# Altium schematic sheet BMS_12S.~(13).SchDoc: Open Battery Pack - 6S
size A3; Author: Morgane Vallée; Revision: 1.0; SheetNumber: 3; SheetTotal: 4
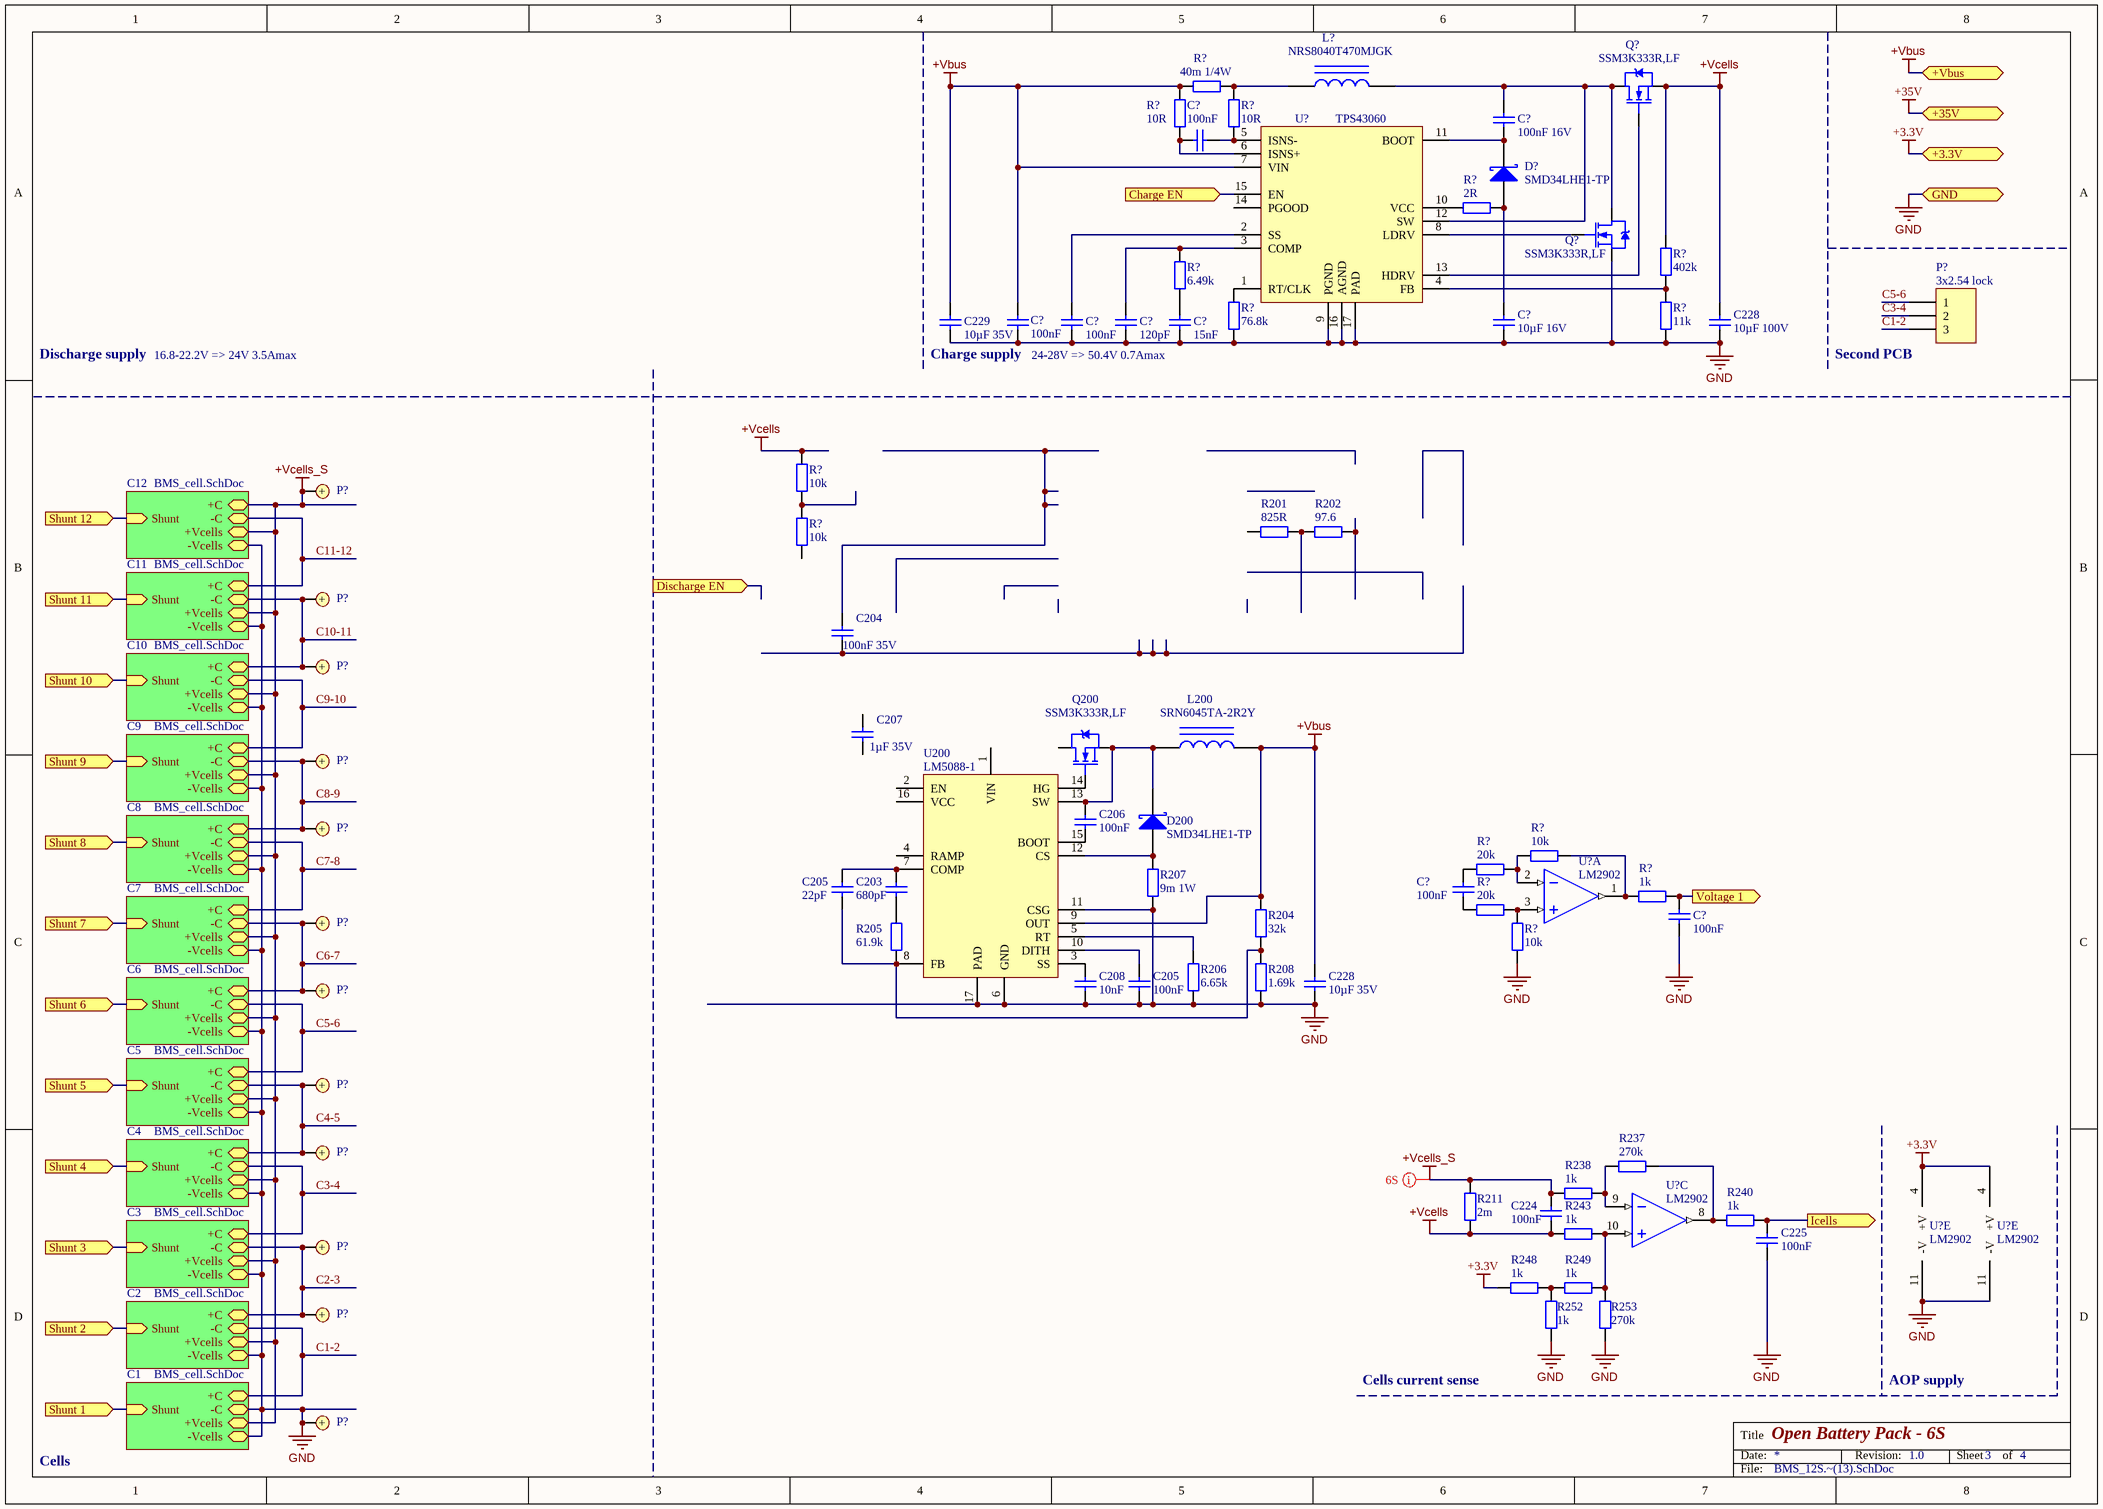
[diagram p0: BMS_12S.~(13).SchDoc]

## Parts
(Parts that share a designator on the sheet are numbered #1, #2 ... from top to bottom, then left to right.)
C203  680pF  [C0603]
C204  100nF 35V  [C0603]
C205#1  22pF  [C0603]
C205#2  100nF  [C0603]
C206  100nF  [C0603]
C207  1µF 35V  [C0805]
C208  10nF  [C0603]
C224  100nF  [C0603]
C225  100nF  [C0603]
C228#1  10µF 100V  [C0603]
C228#2  10µF 35V  [C0603]
C229  10µF 35V  [C0603]
C?#1  100nF 16V  [C0603]
C?#2  100nF  [C0603]
C?#3  100nF  [C0603]
C?#4  120pF  [C0603]
C?#5  15nF  [C0603]
C?#6  10µF 16V  [C0805]
C?#7  100nF  [C0603]
C?#8  100nF  [C0603]
C?#9  100nF  [C0603]
D200  SMD34LHE1-TP  [SOD-123H]
D?  SMD34LHE1-TP  [SOD-123H]
L200  SRN6045TA-2R2Y  [SELF_SMD_8x8]
L?  NRS8040T470MJGK  [SELF_SMD_8x8]
P?#1  3x2.54 lock  [MOLEX KK 0022272031]
P?#2  Bat+  [Keystone 241]  (value not drawn)
P?#3  Bat+  [Keystone 241]  (value not drawn)
P?#4  Bat+  [Keystone 241]  (value not drawn)
P?#5  Bat+  [Keystone 241]  (value not drawn)
P?#6  Bat+  [Keystone 241]  (value not drawn)
P?#7  Bat+  [Keystone 241]  (value not drawn)
P?#8  Bat+  [Keystone 241]  (value not drawn)
P?#9  Bat+  [Keystone 241]  (value not drawn)
P?#10  Bat+  [Keystone 241]  (value not drawn)
P?#11  Bat+  [Keystone 241]  (value not drawn)
P?#12  Bat+  [Keystone 241]  (value not drawn)
P?#13  Bat+  [Keystone 241]  (value not drawn)
Q200  SSM3K333R,LF  [TI SOT-23-3 DBZ]
Q?#1  SSM3K333R,LF  [TI SOT-23-3 DBZ]
Q?#2  SSM3K333R,LF  [TI SOT-23-3 DBZ]
R201  825R  [R0603]
R202  97.6  [R0603]
R204  32k  [R0603]
R205  61.9k  [R0603]
R206  6.65k  [R0603]
R207  9m 1W  [R1206]
R208  1.69k  [R0603]
R211  2m  [R1206]
R237  270k  [R0603]
R238  1k  [R0603]
R240  1k  [R0603]
R243  1k  [R0603]
R248  1k  [R0603]
R249  1k  [R0603]
R252  1k  [R0603]
R253  270k  [R0603]
R?#1  10R  [R0603]
R?#2  40m 1/4W  [R1206]
R?#3  10R  [R0603]
R?#4  2R  [R0603]
R?#5  402k  [R0603]
R?#6  6.49k  [R0603]
R?#7  76.8k  [R0603]
R?#8  11k  [R0603]
R?#9  10k  [R0603]
R?#10  10k  [R0603]
R?#11  10k  [R0603]
R?#12  20k  [R0603]
R?#13  1k  [R0603]
R?#14  20k  [R0603]
R?#15  10k  [R0603]
U200  LM5088-1  [TI MSOP-10 DGQ]
U?#1  TPS43060  [TI WQFN-16 RGH]
U?#2  LM2902  [Atmel SO-14 14S1]  (part A of 5)
U?#3  LM2902  [Atmel SO-14 14S1]  (part C of 5)
U?#4  LM2902  [Atmel SO-14 14S1]  (part E of 5)
U?#5  LM2902  [Atmel SO-14 14S1]  (part E of 5)

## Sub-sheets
C1 = BMS_cell.SchDoc: -C, +C, +Vcells, -Vcells, Shunt (in)
C2 = BMS_cell.SchDoc: -C, +C, +Vcells, -Vcells, Shunt (in)
C3 = BMS_cell.SchDoc: -C, +C, +Vcells, -Vcells, Shunt (in)
C4 = BMS_cell.SchDoc: -C, +C, +Vcells, -Vcells, Shunt (in)
C5 = BMS_cell.SchDoc: -C, +C, +Vcells, -Vcells, Shunt (in)
C6 = BMS_cell.SchDoc: -C, +C, +Vcells, -Vcells, Shunt (in)
C7 = BMS_cell.SchDoc: -C, +C, +Vcells, -Vcells, Shunt (in)
C8 = BMS_cell.SchDoc: -C, +C, +Vcells, -Vcells, Shunt (in)
C9 = BMS_cell.SchDoc: -C, +C, +Vcells, -Vcells, Shunt (in)
C10 = BMS_cell.SchDoc: -C, +C, +Vcells, -Vcells, Shunt (in)
C11 = BMS_cell.SchDoc: -C, +C, +Vcells, -Vcells, Shunt (in)
C12 = BMS_cell.SchDoc: -C, +C, +Vcells, -Vcells, Shunt (in)

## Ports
+3.3V, +35V, +Vbus, Charge EN (in), Discharge EN (in), GND, Icells (out), Shunt 1 (in), Shunt 2 (in), Shunt 3 (in), Shunt 4 (in), Shunt 5 (in), Shunt 6 (in), Shunt 7 (in), Shunt 8 (in), Shunt 9 (in), Shunt 10 (in), Shunt 11 (in), Shunt 12 (in), Voltage 1 (out)

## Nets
+3.3V: R248.2 U?#4.4(+V) U?#5.4(+V) ; port +3.3V
+Vbus: C228#2.1 C229.1 C?#7.2 L200.2 R204.2 R?#1.1 R?#2.2 U200.9(OUT) U?#1.7(VIN) ; port +Vbus
+Vcells: C224.2 C228#1.1 Q?#1.2(S) R211.1 R243.2 R?#5.2 R?#9.2
+Vcells_S: C224.1 P?#2.1 R211.2 R238.1 ; sheet C1/+Vcells, sheet C2/+Vcells, sheet C3/+Vcells, sheet C4/+Vcells, sheet C5/+Vcells, sheet C6/+Vcells, sheet C7/+Vcells, sheet C8/+Vcells, sheet C9/+Vcells, sheet C10/+Vcells, sheet C11/+Vcells, sheet C12/+C, sheet C12/+Vcells
GND: C205#2.2 C208.2 C225.2 C228#1.2 C228#2.2 C229.2 C?#3.2 C?#4.2 C?#5.2 C?#6.2 C?#7.1 C?#9.2 P?#13.1 Q?#2.2(S) R206.1 R207.1 R208.1 R252.2 R253.1 R?#7.1 R?#8.1 R?#15.2 U200.6(GND) U200.11(CSG) U200.17(PAD) U?#1.9(PGND) U?#1.16(AGND) U?#1.17(PAD) U?#4.11(-V) U?#5.11(-V) ; port GND, sheet C1/-C, sheet C1/-Vcells, sheet C2/-Vcells, sheet C3/-Vcells, sheet C4/-Vcells, sheet C5/-Vcells, sheet C6/-Vcells, sheet C7/-Vcells, sheet C8/-Vcells, sheet C9/-Vcells, sheet C10/-Vcells, sheet C11/-Vcells, sheet C12/-Vcells
C1-2: P?#1.3 ; sheet C1/+C, sheet C2/-C
C2-3: P?#11.1 P?#12.1 ; sheet C2/+C, sheet C3/-C
C3-4: P?#1.2 ; sheet C3/+C, sheet C4/-C
C4-5: P?#9.1 P?#10.1 ; sheet C4/+C, sheet C5/-C
C5-6: P?#1.1 ; sheet C5/+C, sheet C6/-C
C6-7: P?#7.1 P?#8.1 ; sheet C6/+C, sheet C7/-C
C7-8: sheet C7/+C, sheet C8/-C
C8-9: P?#5.1 P?#6.1 ; sheet C8/+C, sheet C9/-C
C9-10: sheet C9/+C, sheet C10/-C
C10-11: P?#3.1 P?#4.1 ; sheet C10/+C, sheet C11/-C
C11-12: sheet C11/+C, sheet C12/-C
Charge EN: U?#1.15(EN) ; port Charge EN
Icells: C225.1 R240.1 ; port Icells
Shunt 1: port Shunt 1, sheet C1/Shunt
Shunt 2: port Shunt 2, sheet C2/Shunt
Shunt 3: port Shunt 3, sheet C3/Shunt
Shunt 4: port Shunt 4, sheet C4/Shunt
Shunt 5: port Shunt 5, sheet C5/Shunt
Shunt 6: port Shunt 6, sheet C6/Shunt
Shunt 7: port Shunt 7, sheet C7/Shunt
Shunt 8: port Shunt 8, sheet C8/Shunt
Shunt 9: port Shunt 9, sheet C9/Shunt
Shunt 10: port Shunt 10, sheet C10/Shunt
Shunt 11: port Shunt 11, sheet C11/Shunt
Shunt 12: port Shunt 12, sheet C12/Shunt
Voltage 1: C?#9.1 R?#13.1 ; port Voltage 1
NetC203_1: C203.1 C205#1.1 U200.7(COMP)
NetC203_2: C203.2 R205.2
NetC205#1_2: C205#1.2 R204.1 R205.1 R208.2 U200.8(FB)
NetC205#2_1: C205#2.1 U200.10(DITH)
NetC206_1: C206.1 D200.3(K) L200.1 Q200.2(S) U200.13(SW)
NetC206_2: C206.2 U200.15(BOOT)
NetC208_1: C208.1 U200.3(SS)
NetC?#1_1: C?#1.1 L?.2 Q?#1.3(D) Q?#2.3(D) U?#1.12(SW)
NetC?#1_2: C?#1.2 D?.3(K) U?#1.11(BOOT)
NetC?#2_1: C?#2.1 R?#3.2 U?#1.5(ISNS-)
NetC?#2_2: C?#2.2 R?#1.2 U?#1.6(ISNS+)
NetC?#3_1: C?#3.1 U?#1.2(SS)
NetC?#4_1: C?#4.1 R?#6.2 U?#1.3(COMP)
NetC?#5_1: C?#5.1 R?#6.1
NetC?#6_1: C?#6.1 D?.1(A) R?#4.1
NetC?#8_1: C?#8.1 R?#12.1
NetC?#8_2: C?#8.2 R?#14.2
NetD200_1: D200.1(A) R207.2 U200.12(CS)
NetL?_1: L?.1 R?#2.1 R?#3.1
NetQ200_1: Q200.1(G) U200.14(HG)
NetQ?#1_1: Q?#1.1(G) U?#1.13(HDRV)
NetQ?#2_1: Q?#2.1(G) U?#1.8(LDRV)
NetR201_1: R201.1 R202.2
NetR206_2: R206.2 U200.5(RT)
NetR237_1: R237.1 R240.2 U?#3.8(OUT)
NetR237_2: R237.2 R238.2 U?#3.9(IN-)
NetR243_1: R243.1 R249.1 R253.2 U?#3.10(IN+)
NetR248_1: R248.1 R249.2 R252.1
NetR?#4_2: R?#4.2 U?#1.10(VCC)
NetR?#5_1: R?#5.1 R?#8.2 U?#1.4(FB)
NetR?#7_2: R?#7.2 U?#1.1(RT/CLK)
NetR?#9_1: R?#9.1 R?#10.2
NetR?#11_1: R?#11.1 R?#12.2 U?#2.2(IN-)
NetR?#11_2: R?#11.2 R?#13.2 U?#2.1(OUT)
NetR?#14_1: R?#14.1 R?#15.1 U?#2.3(IN+)

Not connected (* = marked no-connect by the designer): C204 1 2; C207 1 2; Q200 3(D); R201 2; R202 1; R?#10 1; U200 1(VIN) 2(EN) 4(RAMP) 16(VCC); U?#1 14(PGOOD)

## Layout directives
net class 6S: +Vcells_S

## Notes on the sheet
- Discharge supply
- 16.8-22.2V => 24V 3.5Amax
- Charge supply
- (near C?#4) 24-28V => 50.4V 0.7Amax
- (near P?#1) Second PCB
- Cells current sense
- AOP supply
- Cells

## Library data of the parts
C203 C204 C205#1 C205#2 C206-C208 C224 C225 C228#1 C228#2 C229 C?#1-C?#9 = Cap: Capacitor
D200 D? = Diode BAT17
L200 L? = Inductor Iron: Magnetic-Core Inductor
P?#1 = Header 3: Header, 3-Pin
P?#2-P?#13 = Bat+: Battery contact +
Q200 Q?#1 Q?#2 = MOSFET_N
R201 R202 R204-R208 R211 R237 R238 R240 R243 R248 R249 R252 R253 R?#1-R?#15 = Res2: Resistor
U200 = LM5088-1: Wide Input Range Non-Synchronous Buck Controller
U?#1 = TPS43060: Low Quiescent Current Synchronous Boost  DC-DC Controller With Wide VIN Range
U?#2-U?#5 = LM2902: Low-power quad operational amplifiers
